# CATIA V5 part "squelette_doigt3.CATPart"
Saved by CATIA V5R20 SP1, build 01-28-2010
Part number: squelette_doigt3
Publications: "Droite.1", "Droite.2", "Droite.3", "Plan.2"
Bounding box of the stored display mesh (mm): x -20 to 20, y -111.593 to -85.286, z 22.279 to 42.005
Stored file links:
  C:\Users\Fox\Desktop\IAO Projet\A RENDRE\Sauvegarde IFMA\squelette_doigt3.CATPart
  C:\Users\Fox\Desktop\IAO Projet\A RENDRE\Sauvegarde IFMA\squelette.CATProduct
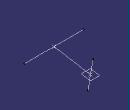
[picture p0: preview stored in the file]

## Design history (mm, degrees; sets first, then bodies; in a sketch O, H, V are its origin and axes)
Set1
  Line1: type PtPt, FirstPoint Point1, SecondPoint Point2
  Line2: type Normal, RefPoint Point1, RefSkin Plane2, Start -20, End 20
  Line3: type Angle, RefPoint Point2, Curve Line1, Support Plane2, Start -10, End 10, Angle 90
  Plane1: type Normal, Curve Line3, RefPoint Point2
Set2
  Point1: linked copy from another document
  Point2: linked copy from another document
  Plane2: linked copy from another document
Body1 (main body)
